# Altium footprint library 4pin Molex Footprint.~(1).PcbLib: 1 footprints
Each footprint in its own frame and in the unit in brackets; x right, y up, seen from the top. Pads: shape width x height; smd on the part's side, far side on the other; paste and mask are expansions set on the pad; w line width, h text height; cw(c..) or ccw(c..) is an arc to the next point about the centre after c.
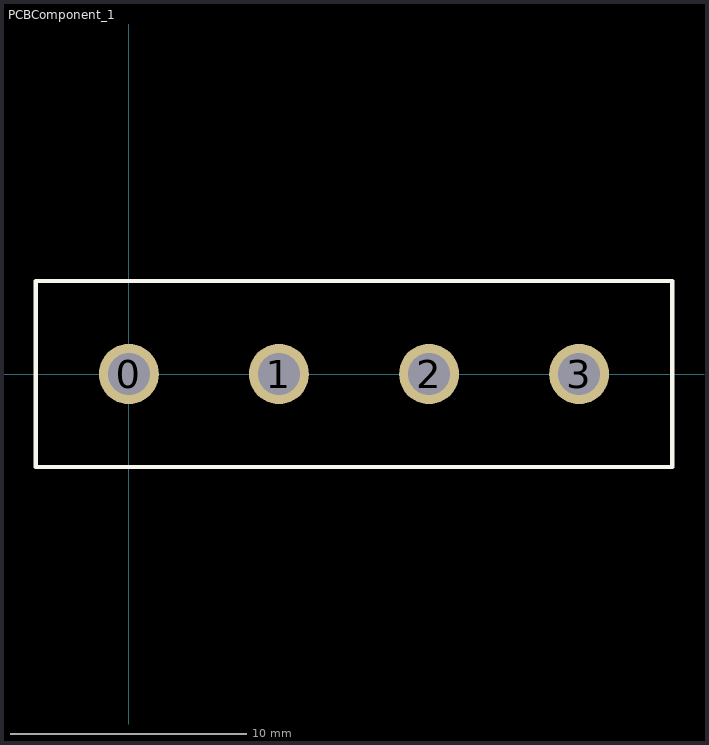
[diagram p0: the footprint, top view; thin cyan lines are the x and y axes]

## PCBComponent_1 [mil]
pads (4):
  round 100 hole 70: 0(0,0) 1(250,0) 2(500,0) 3(750,0)
Top Overlay:
  lines w7: -155,-155 -155,155 905,155 905,-155 -155,-155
